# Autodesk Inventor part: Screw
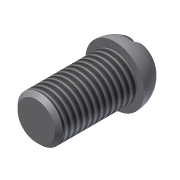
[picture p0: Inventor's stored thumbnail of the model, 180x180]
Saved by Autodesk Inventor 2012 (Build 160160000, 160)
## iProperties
Shininess: 77.0
Length Units: 11269
Angle Units: 11279
Time Units: 11290
Mass Units: 11283
Length Display Precision: 3
Angle Display Precision: 2
Created: 2002-01
Part Number: Screw
Document SubType Name: Modeling
Designer: ***
Density: 1 g/cm^3
Material: Default
Density: 0.0
Volumn: 0.0
Area: 0.0
PropertySet Name: Model Information
Control State: 0
Master: False
Checked Out: False
Author: ***
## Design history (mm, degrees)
sketch "Sketch1"
  geometry: L1 (-0.061, 13.328)-(-0.061, -1.672); L2 (-0.061, -1.672)-(14.939, -1.672); A1 r 15 centre (-0.061, -1.672) between (14.939, -1.672) and (-0.061, 13.328)
  constraints: 4 end point, 2 point on circle, 1 centre point
  dimensions: "d0" = 15 radius of A1
revolve "Revolution1" sketch "Sketch1" stored, may be unused: angle "d3" = 90 deg
workplane "Work Plane2"
sketch "Sketch3"
  geometry: L1 (-3, 26)-(3, 26); L2 (3, 26)-(3, 6); L3 (3, 6)-(-3, 6); L4 (-3, 6)-(-3, 26); L5 (-15, 0)-(15, 0) reference
  constraints: 8 end point, 2 parallel, 1 horizontal, 1 perpendicular
  dimensions: "d11" = 6 distance of L1.start L1.end; "d12" = 20 distance of L3.end L1.start; "d13" = 6 distance between parallel lines of L5 L3; "d14" = 12 distance from line of L4 L5.start
extrude "Extrusion2" cut sketch "Sketch3" stored distance "d15" = 10; taper "d16" = 0 deg
sketch "Sketch4"
  geometry: C1 r 11.5 at (0, 0); C2 r 15 at (0, 0) reference
  constraints: 1 centre point, 1 concentric
  dimensions: "d17" = 23 diameter of C1
extrude "Extrusion3" join sketch "Sketch4" distance "d18" = 40; taper "d19" = 0 deg
chamfer "Chamfer1" distance "d20" = 2; stored, may be unused: second distance "d21" = 2, angle "d24" = 45 deg
thread "Thread1" dims "d22" = 10, "d23" = 0
body "Solid1"
